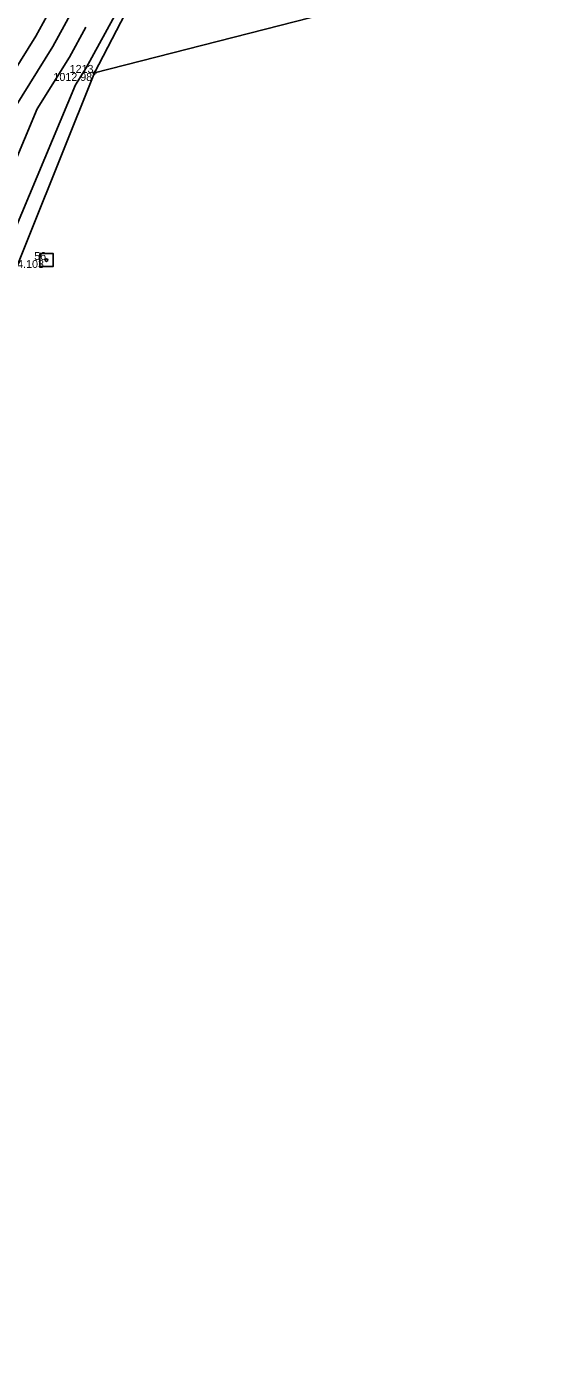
# Model space of a CAD drawing. Extents: x 2354693 to 2355622, y 637071 to 710080.
# Drawn here: x 2355253.6 to 2355330.9, y 708791.8 to 708993.3 of the extents above; entities that cross this region are included whole.
import ezdxf

# ---------------------------------------------------------------- set-up
doc = ezdxf.new("R2010")
doc.units = 0
for name, color, linetype in [('Default', 7, 'Continuous'), ('DT_X_Contour_Major', 7, 'Continuous'), ('DT_X_Contour_Minor', 7, 'Continuous'), ('SV_X_Control_Cells_Found', 7, 'Continuous'), ('SV_X_Shot_Marker', 7, 'Continuous'), ('SV_X_Text_Elevation', 7, 'Continuous'), ('SV_X_Text_Name', 7, 'Continuous'), ('SV_X_Top_of_Bank', 7, 'Continuous')]:
    doc.layers.add(name, color=color, linetype=linetype)

msp = doc.modelspace()

# ---------------------------------------------------------------- linework, layer by layer
at = {"layer": 'Default'}
msp.add_lwpolyline([(2355203.89, 709062.28), (2355168.12, 708973.83), (2355139.21, 708949.25), (2355111.34, 708919.92), (2355085.96, 708873.19), (2355092.11, 708843.77), (2355125.13, 708818.02), (2355154.71, 708803.16), (2355181.45, 708791.76), (2355202.79, 708842.86), (2355225.29, 708890), (2355244.12, 708937.56), (2355263.76, 708986.4), (2355330.91, 709003.61)], dxfattribs=at)
msp.add_lwpolyline([(2355203.89, 709062.28), (2355168.12, 708973.83), (2355139.21, 708949.25), (2355111.34, 708919.92), (2355085.96, 708873.19), (2355092.11, 708843.77), (2355125.13, 708818.02), (2355154.71, 708803.16), (2355181.45, 708791.76), (2355202.79, 708842.86), (2355225.29, 708890), (2355244.12, 708937.56), (2355263.76, 708986.4), (2355330.91, 709003.61)], dxfattribs=at)
at = {"layer": 'DT_X_Contour_Major'}
msp.add_lwpolyline([(2355262.48, 708993.24), (2355260.02, 708988.76), (2355255.18, 708981.03), (2355242.34, 708950.38), (2355235.07, 708934.78), (2355226.34, 708920.36), (2355222.02, 708909.57), (2355220.21, 708902.96)], dxfattribs=at)
msp.add_lwpolyline([(2355262.48, 708993.24), (2355260.02, 708988.76), (2355255.18, 708981.03), (2355242.34, 708950.38), (2355235.07, 708934.78), (2355226.34, 708920.36), (2355222.02, 708909.57), (2355220.21, 708902.96)], dxfattribs=at)
at = {"layer": 'DT_X_Contour_Minor'}
for points in [[(2355285.39, 709028.91), (2355262.53, 708987.18), (2355260.94, 708984.64), (2355243.4, 708942.76), (2355240.45, 708936.43), (2355228.87, 708917.33), (2355227.13, 708912.97), (2355221.28, 708891.6), (2355217.16, 708883.36), (2355197.22, 708846.27), (2355192.4, 708838.49), (2355176.54, 708801.86), (2355173.83, 708795)], [(2355285.39, 709028.91), (2355262.53, 708987.18), (2355260.94, 708984.64), (2355243.4, 708942.76), (2355240.45, 708936.43), (2355228.87, 708917.33), (2355227.13, 708912.97), (2355221.28, 708891.6), (2355217.16, 708883.36), (2355197.22, 708846.27), (2355192.4, 708838.49), (2355176.54, 708801.86), (2355173.83, 708795)], [(2355270.62, 709014.28), (2355257.51, 708990.34), (2355249.42, 708977.42), (2355241.28, 708958), (2355229.69, 708933.13), (2355223.8, 708923.4), (2355216.91, 708906.18), (2355213.74, 708894.61), (2355201.89, 708870.88), (2355190.78, 708850.22), (2355180.4, 708833.43), (2355171.35, 708812.54), (2355165.79, 708798.43)], [(2355270.62, 709014.28), (2355257.51, 708990.34), (2355249.42, 708977.42), (2355241.28, 708958), (2355229.69, 708933.13), (2355223.8, 708923.4), (2355216.91, 708906.18), (2355213.74, 708894.61), (2355201.89, 708870.88), (2355190.78, 708850.22), (2355180.4, 708833.43), (2355171.35, 708812.54), (2355165.79, 708798.43)], [(2355263.24, 709006.97), (2355254.99, 708991.91), (2355243.66, 708973.81), (2355240.23, 708965.62), (2355224.31, 708931.48), (2355221.26, 708926.44), (2355211.79, 708902.78), (2355209.96, 708896.11), (2355194.26, 708864.64), (2355187.56, 708852.19), (2355174.4, 708830.91), (2355168.76, 708817.88), (2355161.76, 708800.15)], [(2355263.24, 709006.97), (2355254.99, 708991.91), (2355243.66, 708973.81), (2355240.23, 708965.62), (2355224.31, 708931.48), (2355221.26, 708926.44), (2355211.79, 708902.78), (2355209.96, 708896.11), (2355194.26, 708864.64), (2355187.56, 708852.19), (2355174.4, 708830.91), (2355168.76, 708817.88), (2355161.76, 708800.15)]]:
    msp.add_lwpolyline(points, dxfattribs=at)
at = {"layer": 'SV_X_Control_Cells_Found'}
msp.add_lwpolyline([(2355255.58, 708959.34), (2355257.56, 708959.34), (2355257.56, 708957.36), (2355255.58, 708957.36), (2355255.58, 708959.34)], dxfattribs=at)
msp.add_circle((2355256.57, 708958.35), 0.2, dxfattribs=at)
at = {"layer": 'SV_X_Shot_Marker'}
for p, q in [((2355264.06, 708986.4), (2355263.46, 708986.4)), ((2355263.76, 708986.7), (2355263.76, 708986.1))]:
    msp.add_line(p, q, dxfattribs=at)
at = {"layer": 'SV_X_Top_of_Bank'}
msp.add_lwpolyline([(2355286.26, 709029.77), (2355263.76, 708986.4), (2355244.12, 708937.56), (2355230.59, 708915.27), (2355225.29, 708890), (2355202.79, 708842.86), (2355181.45, 708791.76)], dxfattribs=at)

# ---------------------------------------------------------------- texts
at = {"layer": 'SV_X_Text_Elevation'}
for s, p in [('1012.98', (2355257.62, 708985.2)), ('1014.103', (2355249.5, 708957.15))]:
    msp.add_text(s, height=1.2, dxfattribs=at).set_placement(p)
at = {"layer": 'SV_X_Text_Name'}
for s, p in [('1213', (2355260.05, 708986.4)), ('56', (2355254.73, 708958.35))]:
    msp.add_text(s, height=1.2, dxfattribs=at).set_placement(p)

doc.saveas('drawing.dxf')
